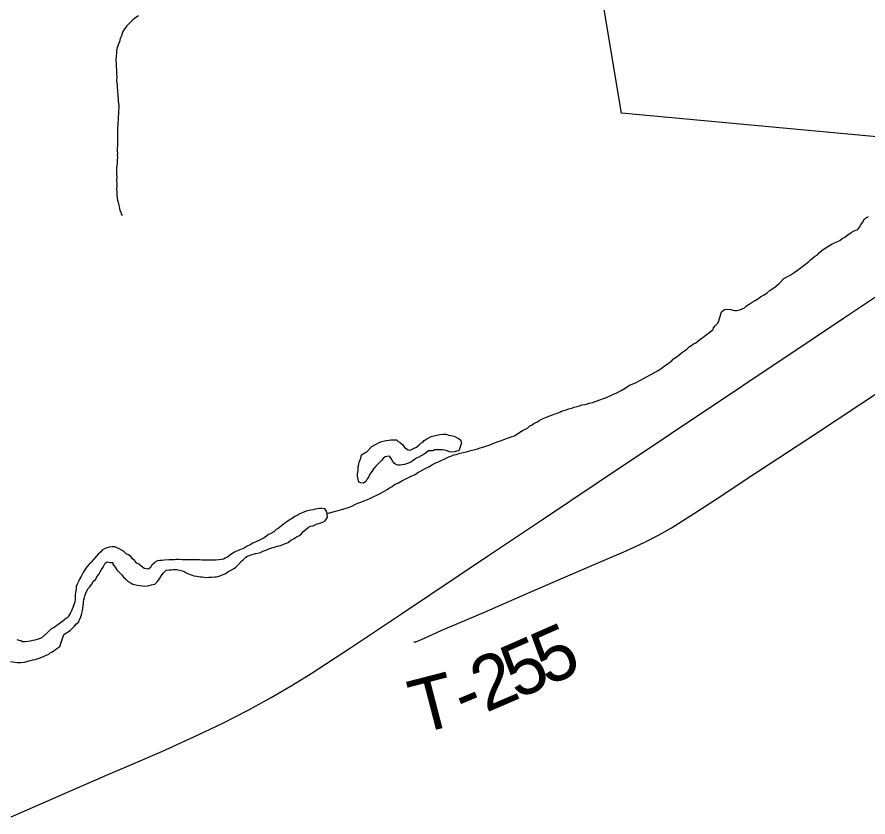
# Model space of a CAD drawing. Extents: x -19.5 to 44.1, y 0 to 22.
# Drawn here: x -14.727 to -13.829, y 5.747 to 6.591 of the extents above; entities that cross this region are included whole.
import ezdxf

# ---------------------------------------------------------------- set-up
doc = ezdxf.new("R2010")
doc.units = 0
for name, color, linetype in [('GM_X_Minor_Lake', 7, 'Continuous'), ('GM_X_Minor_River', 7, 'Continuous'), ('GM_X_Township', 7, 'Continuous'), ('GM_X_Township_Road', 7, 'Continuous'), ('GM_X_Township_Road_Text', 7, 'Continuous'), ('GM_X_US_Route', 7, 'Continuous')]:
    doc.layers.add(name, color=color, linetype=linetype)

msp = doc.modelspace()

# ---------------------------------------------------------------- linework, layer by layer
at = {"layer": 'GM_X_Minor_Lake'}
msp.add_lwpolyline([(-14.36732, 6.10695), (-14.36728, 6.1093), (-14.36684, 6.11272), (-14.36681, 6.11462), (-14.36677, 6.1169), (-14.36597, 6.11954), (-14.36555, 6.12181), (-14.36475, 6.12408), (-14.36396, 6.12597), (-14.36314, 6.12937), (-14.35967, 6.13159), (-14.35775, 6.1327), (-14.35233, 6.13831), (-14.34849, 6.14014), (-14.34465, 6.14236), (-14.34196, 6.14345), (-14.3389, 6.14416), (-14.33699, 6.14451), (-14.33432, 6.14484), (-14.33241, 6.14519), (-14.32823, 6.14511), (-14.32632, 6.14508), (-14.32444, 6.14353), (-14.32218, 6.14197), (-14.31955, 6.14003), (-14.3177, 6.13695), (-14.31393, 6.13461), (-14.31203, 6.1342), (-14.30781, 6.1364), (-14.30512, 6.1375), (-14.30241, 6.14011), (-14.30049, 6.1416), (-14.29856, 6.14271), (-14.29701, 6.14458), (-14.29431, 6.14643), (-14.28971, 6.14863), (-14.28703, 6.14935), (-14.28512, 6.14969), (-14.28244, 6.15041), (-14.28053, 6.15076), (-14.2771, 6.15108), (-14.27405, 6.15103), (-14.2714, 6.15022), (-14.26874, 6.14979), (-14.26533, 6.14897), (-14.26307, 6.14779), (-14.26118, 6.147), (-14.25892, 6.14506), (-14.25783, 6.14201), (-14.25864, 6.13898), (-14.25944, 6.13671), (-14.26063, 6.13369), (-14.26292, 6.13335), (-14.26522, 6.13263), (-14.26789, 6.1323), (-14.27055, 6.13272), (-14.27282, 6.13352), (-14.27548, 6.13433), (-14.27775, 6.13475), (-14.28004, 6.13479), (-14.28232, 6.13483), (-14.28613, 6.13451), (-14.28805, 6.13378), (-14.29262, 6.13348), (-14.29455, 6.132), (-14.29725, 6.13014), (-14.30033, 6.12829), (-14.3034, 6.12645), (-14.30532, 6.12572), (-14.30724, 6.12461), (-14.3111, 6.12164), (-14.31378, 6.12054), (-14.3157, 6.11982), (-14.318, 6.1191), (-14.32029, 6.11876), (-14.3222, 6.11841), (-14.32448, 6.11845), (-14.32638, 6.11886), (-14.32826, 6.12041), (-14.33013, 6.12235), (-14.33198, 6.12542), (-14.33384, 6.12811), (-14.33651, 6.12778), (-14.33842, 6.12743), (-14.34036, 6.12556), (-14.3423, 6.12332), (-14.34501, 6.1207), (-14.34811, 6.11733), (-14.35044, 6.11472), (-14.35161, 6.11284), (-14.35317, 6.11058), (-14.35512, 6.10796), (-14.35553, 6.10606), (-14.35708, 6.10419), (-14.35866, 6.10118), (-14.36097, 6.09932), (-14.36401, 6.09975), (-14.3659, 6.10054), (-14.36732, 6.10695)], dxfattribs=at)
at = {"layer": 'GM_X_Minor_River'}
for points in [[(-14.59838, 6.59259), (-14.60146, 6.59075), (-14.60454, 6.58852), (-14.61074, 6.58217), (-14.61307, 6.57917), (-14.61503, 6.57616), (-14.61583, 6.57389), (-14.61662, 6.57163), (-14.61782, 6.56861), (-14.61864, 6.5652), (-14.61983, 6.56218), (-14.62063, 6.55992), (-14.62142, 6.55803), (-14.62185, 6.555), (-14.62188, 6.5531), (-14.62193, 6.55044), (-14.62238, 6.54627), (-14.62207, 6.5417), (-14.62212, 6.53866), (-14.62179, 6.53562), (-14.62186, 6.53182), (-14.62154, 6.52801), (-14.6216, 6.52421), (-14.62092, 6.51964), (-14.62097, 6.5166), (-14.62062, 6.51431), (-14.62067, 6.51166), (-14.62032, 6.50975), (-14.62036, 6.50747), (-14.62001, 6.50518), (-14.62006, 6.50252), (-14.61972, 6.50024), (-14.61938, 6.49757), (-14.61942, 6.49529), (-14.61946, 6.49301), (-14.61951, 6.48997), (-14.61995, 6.48618)], [(-14.61995, 6.48618), (-14.62001, 6.48276), (-14.62043, 6.48011), (-14.62047, 6.47783), (-14.62052, 6.47479), (-14.62056, 6.47213), (-14.62061, 6.46909), (-14.62067, 6.46567), (-14.62084, 6.45542), (-14.62089, 6.45276), (-14.62093, 6.4501), (-14.62059, 6.44743), (-14.62101, 6.44554), (-14.62066, 6.44326), (-14.62109, 6.4406), (-14.62115, 6.4368), (-14.62161, 6.43225), (-14.62171, 6.42617), (-14.62139, 6.42237), (-14.62183, 6.41895), (-14.6215, 6.41553), (-14.62155, 6.41249), (-14.62159, 6.41059), (-14.62128, 6.4064), (-14.62133, 6.40337), (-14.621, 6.40032), (-14.62065, 6.39803), (-14.61992, 6.39612), (-14.61957, 6.39421), (-14.61886, 6.39154), (-14.61851, 6.38926), (-14.61817, 6.38735), (-14.61705, 6.38543), (-14.61671, 6.38352), (-14.61558, 6.38237)], [(-14.08936, 6.19739), (-14.08513, 6.1996), (-14.08051, 6.20294), (-14.07399, 6.20549), (-14.069, 6.20806), (-14.06438, 6.21065), (-14.05324, 6.21653), (-14.05017, 6.21838), (-14.04708, 6.22061), (-14.044, 6.22283), (-14.04169, 6.22431), (-14.03937, 6.22618), (-14.03629, 6.2284), (-14.03397, 6.23064), (-14.03127, 6.2325), (-14.02857, 6.23473), (-14.02549, 6.23696), (-14.0224, 6.23918), (-14.02009, 6.24104), (-14.01739, 6.24328), (-14.01469, 6.24513), (-14.01276, 6.24662), (-14.01046, 6.24772), (-14.00621, 6.25107), (-14.0039, 6.25293), (-14.00159, 6.25441), (-13.99927, 6.25627), (-13.99696, 6.25775), (-13.99503, 6.25962), (-13.99233, 6.26147), (-13.99192, 6.26336), (-13.98959, 6.26598), (-13.98727, 6.26822), (-13.98608, 6.27086), (-13.98326, 6.28031), (-13.98017, 6.28292), (-13.97826, 6.28327), (-13.9737, 6.28281), (-13.97143, 6.28201), (-13.96915, 6.28159), (-13.96725, 6.28156), (-13.96419, 6.28226), (-13.9615, 6.28336), (-13.9592, 6.28446), (-13.95688, 6.2867), (-13.95418, 6.28855), (-13.9511, 6.2904), (-13.94803, 6.29225), (-13.94495, 6.29409), (-13.94226, 6.29595), (-13.93918, 6.2978), (-13.93571, 6.30002), (-13.93186, 6.30299), (-13.92723, 6.30633), (-13.9226, 6.31005), (-13.91756, 6.31529), (-13.91103, 6.31897), (-13.90679, 6.32194), (-13.90333, 6.32416), (-13.90024, 6.32639), (-13.89754, 6.32862), (-13.89484, 6.33047), (-13.89137, 6.33346), (-13.88943, 6.33532), (-13.8875, 6.33681), (-13.88519, 6.33867), (-13.88211, 6.34052), (-13.88018, 6.34238), (-13.87747, 6.345), (-13.874, 6.3476), (-13.86669, 6.35203), (-13.86477, 6.35276), (-13.8617, 6.35423), (-13.85863, 6.35569), (-13.85593, 6.35755), (-13.85324, 6.35902), (-13.85015, 6.36163), (-13.84669, 6.36385), (-13.844, 6.36532), (-13.8417, 6.36643), (-13.83979, 6.36677), (-13.83783, 6.36978), (-13.83627, 6.37203), (-13.8347, 6.37466), (-13.83236, 6.37842), (-13.83043, 6.37991), (-13.82812, 6.38101)], [(-14.39958, 6.06744), (-14.38275, 6.07209), (-14.3793, 6.07317), (-14.37586, 6.07425), (-14.37279, 6.07572), (-14.3701, 6.07681), (-14.36703, 6.07828), (-14.36397, 6.07937), (-14.36052, 6.08083), (-14.35706, 6.08229), (-14.35361, 6.08375), (-14.34363, 6.08852), (-14.34094, 6.08999), (-14.33863, 6.09147), (-14.33632, 6.09295), (-14.33363, 6.09443), (-14.33094, 6.0959), (-14.32824, 6.09813), (-14.32402, 6.09996), (-14.32056, 6.1018), (-14.31711, 6.10364), (-14.31365, 6.10548), (-14.31019, 6.10732), (-14.30674, 6.10878), (-14.30366, 6.11063), (-14.30097, 6.1121), (-14.29789, 6.11395), (-14.2952, 6.11543), (-14.29213, 6.11689), (-14.28829, 6.11911), (-14.28483, 6.12095), (-14.28138, 6.12241), (-14.27831, 6.12388), (-14.27524, 6.12534), (-14.27255, 6.12644), (-14.27025, 6.12754), (-14.26796, 6.12826), (-14.26565, 6.12936), (-14.26336, 6.1297), (-14.26106, 6.13042), (-14.25915, 6.13115), (-14.25609, 6.13185), (-14.2538, 6.13219), (-14.2515, 6.13292), (-14.24883, 6.13363), (-14.24653, 6.13435), (-14.24347, 6.13506), (-14.2408, 6.13577), (-14.23811, 6.13687), (-14.23505, 6.13757), (-14.23199, 6.13866), (-14.22854, 6.13974), (-14.22356, 6.14156), (-14.22011, 6.14302), (-14.21666, 6.1441), (-14.21321, 6.14556), (-14.21015, 6.14665), (-14.20709, 6.14773), (-14.2044, 6.14883), (-14.20173, 6.14954), (-14.19941, 6.15102), (-14.19326, 6.15509), (-14.19018, 6.15656), (-14.18787, 6.15804), (-14.18556, 6.1599), (-14.18326, 6.161), (-14.18094, 6.16286), (-14.17826, 6.16396), (-14.17595, 6.16544), (-14.17364, 6.16654), (-14.17172, 6.16765), (-14.16981, 6.16837), (-14.1675, 6.16947), (-14.16444, 6.17056), (-14.16176, 6.17165), (-14.15984, 6.17238), (-14.15754, 6.1731), (-14.15409, 6.17456), (-14.15217, 6.17529), (-14.14988, 6.17601), (-14.1472, 6.17672), (-14.14451, 6.17782), (-14.14146, 6.17853), (-14.13877, 6.17962), (-14.13572, 6.18033), (-14.13304, 6.18104), (-14.13036, 6.18214), (-14.12769, 6.18247), (-14.12577, 6.18282), (-14.12309, 6.18391), (-14.11965, 6.18461), (-14.11659, 6.1857), (-14.11467, 6.18643), (-14.11161, 6.18751), (-14.10777, 6.18897), (-14.10471, 6.19006), (-14.09819, 6.19298), (-14.09397, 6.19481), (-14.08936, 6.19739)], [(-14.46535, 6.02829), (-14.46305, 6.02901), (-14.46113, 6.03011), (-14.45768, 6.03119), (-14.455, 6.03191), (-14.45232, 6.033), (-14.45003, 6.03334), (-14.44773, 6.03406), (-14.44543, 6.03516), (-14.44351, 6.03589), (-14.44045, 6.03698), (-14.43775, 6.03921), (-14.43506, 6.04069), (-14.43313, 6.04179), (-14.43121, 6.04328), (-14.42929, 6.04401), (-14.42659, 6.04586), (-14.42465, 6.04849), (-14.42194, 6.05072), (-14.41963, 6.05258), (-14.41694, 6.05405), (-14.41426, 6.05439), (-14.41196, 6.05549), (-14.41004, 6.0566), (-14.40813, 6.05694), (-14.40621, 6.05767), (-14.40392, 6.05839), (-14.40161, 6.05987), (-14.40005, 6.06175), (-14.39926, 6.06363), (-14.39958, 6.06744), (-14.40067, 6.0705), (-14.40178, 6.07241), (-14.4052, 6.07285), (-14.40748, 6.07289), (-14.40978, 6.07255), (-14.41206, 6.07221), (-14.41436, 6.07149), (-14.41665, 6.07115), (-14.42162, 6.07009), (-14.42584, 6.06827), (-14.42891, 6.0668), (-14.43122, 6.06532), (-14.43352, 6.06422), (-14.43622, 6.06237), (-14.43852, 6.06126), (-14.44199, 6.05866), (-14.44508, 6.05644), (-14.44816, 6.05421), (-14.45125, 6.0516), (-14.45317, 6.0505), (-14.45587, 6.04826), (-14.45895, 6.04641), (-14.46125, 6.04531), (-14.46357, 6.04345), (-14.46588, 6.04197), (-14.46818, 6.04087), (-14.47087, 6.0394), (-14.47471, 6.03756), (-14.47778, 6.0361), (-14.48086, 6.03425), (-14.48392, 6.03316), (-14.48701, 6.03094), (-14.48892, 6.03021), (-14.49275, 6.02876), (-14.49736, 6.02655), (-14.50005, 6.02508), (-14.50237, 6.02322), (-14.50468, 6.02136), (-14.50698, 6.02026), (-14.50891, 6.01915), (-14.51082, 6.0188), (-14.51387, 6.01848), (-14.5173, 6.01816), (-14.51959, 6.0182), (-14.52225, 6.01824), (-14.52491, 6.01829), (-14.52758, 6.01833), (-14.52986, 6.01837), (-14.53177, 6.0184), (-14.53405, 6.01844), (-14.53595, 6.01848), (-14.53824, 6.01852), (-14.54128, 6.01857), (-14.54395, 6.01862), (-14.54585, 6.01865), (-14.54776, 6.01868), (-14.54966, 6.01871), (-14.55233, 6.01876), (-14.55575, 6.01882), (-14.5588, 6.01887), (-14.56071, 6.01852), (-14.56337, 6.01857), (-14.56604, 6.01861), (-14.57137, 6.01833), (-14.57366, 6.01798), (-14.57594, 6.01802), (-14.57823, 6.01768), (-14.58015, 6.01696), (-14.58209, 6.01509), (-14.58441, 6.01285)], [(-14.67714, 5.93994), (-14.67047, 5.94402), (-14.66891, 5.9459), (-14.66621, 5.94851), (-14.66388, 5.95113), (-14.66156, 5.95299), (-14.66115, 5.95489), (-14.65958, 5.95752), (-14.65877, 5.96054), (-14.65836, 5.96244), (-14.65755, 5.96508), (-14.65714, 5.96736), (-14.65708, 5.9704), (-14.65667, 5.97229), (-14.65664, 5.97419), (-14.65622, 5.97646), (-14.65542, 5.97873), (-14.65501, 5.98062), (-14.65341, 5.98515), (-14.65146, 5.98816), (-14.64991, 5.99003), (-14.64796, 5.99266), (-14.64638, 5.99567), (-14.64406, 5.99791), (-14.64171, 6.00167), (-14.64015, 6.00393), (-14.63898, 6.00581), (-14.63741, 6.00844), (-14.63585, 6.01069), (-14.63467, 6.01295), (-14.63387, 6.01522), (-14.63157, 6.01632), (-14.62815, 6.01588), (-14.62548, 6.01583), (-14.62552, 6.01393), (-14.62328, 6.01086), (-14.62142, 6.00816), (-14.61955, 6.00623), (-14.61618, 6.00275), (-14.61432, 6.00044), (-14.6117, 5.99774), (-14.60944, 5.9958), (-14.60643, 5.99385), (-14.60454, 5.99305), (-14.60264, 5.99264), (-14.59961, 5.99183), (-14.59695, 5.9914), (-14.59429, 5.99098), (-14.59201, 5.99094), (-14.58934, 5.99127), (-14.58743, 5.99162), (-14.58475, 5.99233), (-14.58131, 5.99304), (-14.57899, 5.99528), (-14.57744, 5.99715), (-14.57587, 5.9994), (-14.57431, 6.00204), (-14.57236, 6.00466), (-14.56926, 6.00765), (-14.56621, 6.00797), (-14.56393, 6.00794), (-14.56202, 6.00828), (-14.55859, 6.00822), (-14.55517, 6.00779), (-14.55214, 6.00697), (-14.55025, 6.00618), (-14.54837, 6.00501), (-14.54496, 6.00343), (-14.54194, 6.00224), (-14.54004, 6.00183), (-14.537, 6.0014), (-14.5351, 6.00098), (-14.53321, 6.00057), (-14.5313, 6.00054), (-14.52941, 6.00012), (-14.52712, 6.00008), (-14.52445, 6.00042), (-14.52141, 6.00037), (-14.51797, 6.00069), (-14.51607, 6.00065), (-14.51339, 6.00137), (-14.51109, 6.00247), (-14.50917, 6.0032), (-14.50649, 6.00429), (-14.50379, 6.00615), (-14.50149, 6.00725), (-14.49841, 6.00909), (-14.49572, 6.01095), (-14.49262, 6.01393), (-14.4899, 6.01731), (-14.48798, 6.01841), (-14.48526, 6.02141), (-14.48334, 6.02251), (-14.47951, 6.02397), (-14.47721, 6.02469), (-14.47491, 6.02541), (-14.47262, 6.02575), (-14.46995, 6.02646), (-14.46726, 6.02756), (-14.46535, 6.02829)], [(-14.58441, 6.01285), (-14.58558, 6.01097), (-14.58791, 6.00873), (-14.59018, 6.00915), (-14.59246, 6.00957), (-14.59434, 6.01074), (-14.59622, 6.01229), (-14.5981, 6.01384), (-14.60037, 6.01502), (-14.60261, 6.01772), (-14.60486, 6.01966), (-14.60673, 6.02197), (-14.60898, 6.02391), (-14.61162, 6.02509), (-14.61349, 6.02703), (-14.61575, 6.02859), (-14.61877, 6.03016), (-14.62104, 6.03134), (-14.62369, 6.03214), (-14.62636, 6.03219), (-14.62941, 6.03186), (-14.63208, 6.03115), (-14.63439, 6.03005), (-14.63669, 6.02895), (-14.63863, 6.0267), (-14.64095, 6.02446), (-14.64366, 6.02184), (-14.64833, 6.01622), (-14.65065, 6.01398), (-14.65298, 6.01137), (-14.65454, 6.00911), (-14.65572, 6.00685), (-14.65728, 6.0046), (-14.65887, 6.00083), (-14.66081, 5.9982), (-14.662, 5.99556), (-14.66318, 5.99292), (-14.66437, 5.99028), (-14.66441, 5.98762), (-14.66485, 5.98421), (-14.66527, 5.98194), (-14.66531, 5.97928), (-14.66537, 5.97624), (-14.66578, 5.97434), (-14.66658, 5.97208), (-14.66778, 5.9683), (-14.66936, 5.96491), (-14.67016, 5.96264), (-14.67211, 5.96001), (-14.6729, 5.95813), (-14.67705, 5.95518)], [(-14.72683, 5.9345), (-14.72494, 5.93371), (-14.72267, 5.9333), (-14.72078, 5.93251), (-14.7185, 5.93248), (-14.71508, 5.93281), (-14.7128, 5.93316), (-14.71013, 5.93388), (-14.70747, 5.93422), (-14.70519, 5.93495), (-14.7029, 5.93567), (-14.70023, 5.93678), (-14.69447, 5.94201), (-14.69255, 5.94389), (-14.69062, 5.94576), (-14.68795, 5.94724), (-14.68565, 5.94911), (-14.68373, 5.95022), (-14.68067, 5.95245), (-14.67705, 5.95518)], [(-14.73358, 5.91142), (-14.72638, 5.91017), (-14.72448, 5.91015), (-14.72258, 5.91012), (-14.71878, 5.91044), (-14.71649, 5.91117), (-14.71421, 5.9119), (-14.7123, 5.91225), (-14.7104, 5.91298), (-14.70773, 5.91333), (-14.70545, 5.91405), (-14.70316, 5.91478), (-14.70049, 5.91588), (-14.6982, 5.91699), (-14.69591, 5.9181), (-14.69323, 5.9192), (-14.69132, 5.92069), (-14.68941, 5.92142), (-14.68481, 5.92515), (-14.68137, 5.92701), (-14.67714, 5.93994)]]:
    msp.add_lwpolyline(points, dxfattribs=at)
at = {"layer": 'GM_X_Township'}
msp.add_lwpolyline([(-12.89135, 6.37944), (-13.11367, 6.40414), (-13.35833, 6.42942), (-13.44114, 6.43455), (-13.5998, 6.44439), (-14.08907, 6.4899), (-14.17771, 7.02314), (-14.28499, 7.03495), (-14.65899, 7.08304), (-15.5678, 7.21413), (-15.56001, 7.19629), (-16.11933, 6.86064), (-16.1939, 6.81589), (-16.21334, 6.81208), (-16.897, 6.44106), (-17.1473, 6.30523)], dxfattribs=at)
at = {"layer": 'GM_X_Township_Road'}
msp.add_lwpolyline([(-14.30817, 5.932), (-14.30737, 5.9319), (-14.30642, 5.93192), (-14.30589, 5.932), (-14.3051, 5.93227), (-14.29975, 5.93451), (-14.27904, 5.94393), (-14.23337, 5.9635), (-14.18779, 5.98333), (-14.14782, 6.00047), (-14.10796, 6.01785), (-14.08399, 6.0282), (-14.06422, 6.03733), (-14.04982, 6.04474), (-14.03629, 6.05244), (-14.01681, 6.0647), (-13.99023, 6.08196), (-13.94819, 6.1096), (-13.88636, 6.15017), (-13.78417, 6.21753)], dxfattribs=at)
at = {"layer": 'GM_X_US_Route'}
for points in [[(-14.6091, 5.80121), (-14.574, 5.81641), (-14.53546, 5.83378), (-14.50966, 5.84614), (-14.48195, 5.86022), (-14.45854, 5.87318), (-14.43552, 5.88676), (-14.41647, 5.89853), (-14.3748, 5.92566), (-14.32641, 5.95821), (-14.32117, 5.96174), (-14.23016, 6.02234), (-14.17132, 6.0618), (-14.1145, 6.09978), (-14.03707, 6.15165), (-13.88577, 6.25291), (-13.85472, 6.27353), (-13.80205, 6.30879), (-13.66417, 6.40106), (-13.5998, 6.44438)], [(-14.73294, 5.74723), (-14.67672, 5.77217), (-14.63217, 5.79123), (-14.6091, 5.80121)]]:
    msp.add_lwpolyline(points, dxfattribs=at)

# ---------------------------------------------------------------- texts
at = {"layer": 'GM_X_Township_Road_Text'}
for s, rotation, p in [('5', 23.69984, (-14.16733, 5.88498)), ('5', 23.5968, (-14.19951, 5.87093)), ('2', 23.16615, (-14.23211, 5.85698)), ('T', 14.49773, (-14.30366, 5.83433)), ('-', 22.64605, (-14.25417, 5.84778))]:
    msp.add_text(s, height=0.05682, rotation=rotation, dxfattribs=at).set_placement(p)

doc.saveas('drawing.dxf')
